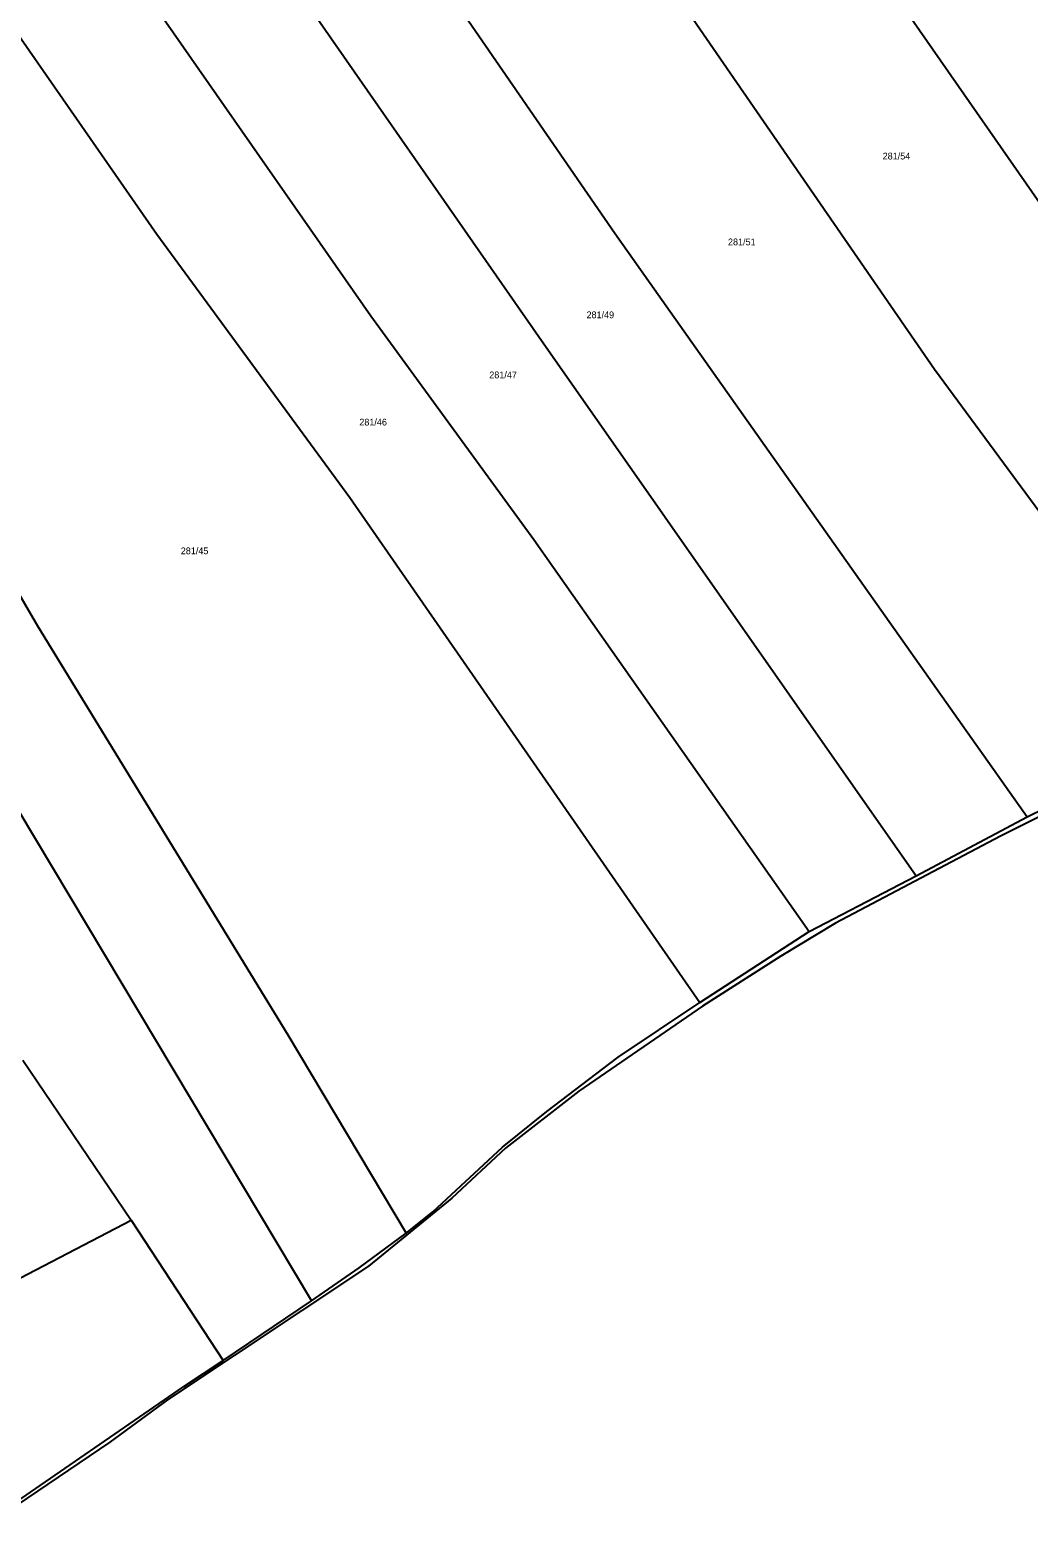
# Model space of a CAD drawing. Extents: x -780000 to -777378, y -1011169 to -1009297.
# Drawn here: x -778149.1 to -777897.6, y -1011100.8 to -1010721.1 of the extents above; entities that cross this region are included whole.
import ezdxf

# ---------------------------------------------------------------- set-up
doc = ezdxf.new("R2010")
doc.units = 0
doc.layers.add('KN_HRANICE', color=7, linetype='Continuous')
doc.layers.add('KN_PARCELY', color=7, linetype='Continuous')

msp = doc.modelspace()

# ---------------------------------------------------------------- linework, layer by layer
at = {"layer": 'KN_HRANICE'}
for p, q in [((-778087.99, -1010647.3), (-778001.85, -1010772.26)), ((-778115.74, -1010662.1), (-778021.13, -1010798.24)), ((-778143.85, -1010677.34), (-778063.35, -1010793.06)), ((-778173.03, -1010692.24), (-778117.21, -1010772.54)), ((-777935.33, -1010706.44), (-777864.34, -1010808.65)), ((-777983.83, -1010715.92), (-777921.4, -1010806.5)), ((-778233.17, -1010724.47), (-778147.23, -1010871.18)), ((-778117.21, -1010772.54), (-778068.65, -1010838.85)), ((-778001.85, -1010772.26), (-777898.07, -1010919.25)), ((-778063.35, -1010793.06), (-778022.29, -1010849.42)), ((-778021.13, -1010798.24), (-777926.01, -1010934.1)), ((-777921.4, -1010806.5), (-777893.7, -1010844.14)), ((-778068.65, -1010838.85), (-777980.49, -1010965.98)), ((-778022.29, -1010849.42), (-777952.91, -1010948.15)), ((-778147.23, -1010871.18), (-778084.18, -1010974.16)), ((-777898.07, -1010919.25), (-777855.82, -1010898.56)), ((-778156.55, -1010910.11), (-778078.29, -1011041.12)), ((-777893.68, -1010918.59), (-777904.75, -1010924.16)), ((-777926.01, -1010934.1), (-777898.07, -1010919.25)), ((-777904.75, -1010924.16), (-777946.29, -1010946.05)), ((-777952.91, -1010948.15), (-777926.01, -1010934.1)), ((-777980.49, -1010965.98), (-777952.91, -1010948.15)), ((-777946.29, -1010946.05), (-777960.11, -1010954.32)), ((-777960.11, -1010954.32), (-777979.84, -1010966.89)), ((-777979.84, -1010966.89), (-778010.92, -1010988.32)), ((-778001.04, -1010979.74), (-777980.49, -1010965.98)), ((-778084.18, -1010974.16), (-778054.46, -1011024.11)), ((-778150.99, -1010980.51), (-778123.71, -1011020.78)), ((-778018.96, -1010993.43), (-778001.04, -1010979.74)), ((-778010.92, -1010988.32), (-778029.41, -1011002.72)), ((-778030.19, -1011002.43), (-778018.96, -1010993.43)), ((-778047.71, -1011018.72), (-778030.19, -1011002.43)), ((-778029.41, -1011002.72), (-778042.94, -1011015.24)), ((-778042.94, -1011015.24), (-778063.87, -1011032.42)), ((-778232.23, -1011077.49), (-778123.71, -1011020.78)), ((-778123.71, -1011020.78), (-778100.49, -1011056.2)), ((-778054.46, -1011024.11), (-778047.71, -1011018.72)), ((-778066.28, -1011032.84), (-778054.46, -1011024.11)), ((-778063.87, -1011032.42), (-778114.5, -1011066.06)), ((-778078.29, -1011041.12), (-778066.28, -1011032.84)), ((-778100.49, -1011056.2), (-778078.29, -1011041.12)), ((-778110.44, -1011062.73), (-778100.49, -1011056.2)), ((-778164.52, -1011099.92), (-778110.44, -1011062.73)), ((-778114.5, -1011066.06), (-778129.05, -1011076.74)), ((-778129.05, -1011076.74), (-778164.73, -1011100.82))]:
    msp.add_line(p, q, dxfattribs=at)

# ---------------------------------------------------------------- texts
at = {"layer": 'KN_PARCELY'}
for s, p in [('281/54', (-777934.43, -1010753.71)), ('281/51', (-777973.38, -1010775.32)), ('281/49', (-778009.01, -1010793.69)), ('281/47', (-778033.49, -1010808.81)), ('281/46', (-778066.22, -1010820.7)), ('281/45', (-778111.18, -1010853.12))]:
    msp.add_text(s, height=1.7, dxfattribs=at).set_placement(p)

doc.saveas('drawing.dxf')
